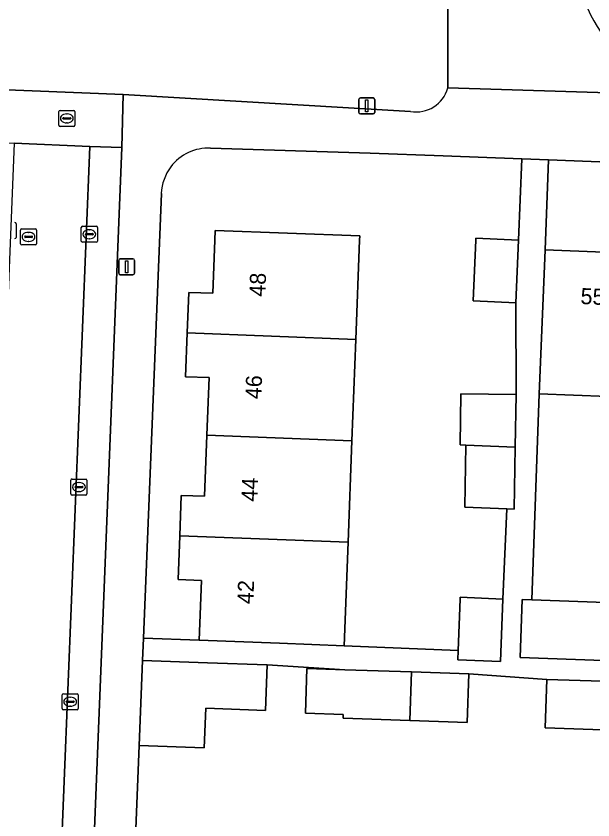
# Model space of a CAD drawing. Extents: x 160732 to 162107, y 387428 to 388479.
# Drawn here: x 161266.5 to 161302.4, y 387713.9 to 387764 of the extents above; entities that cross this region are included whole.
import ezdxf

# ---------------------------------------------------------------- set-up
doc = ezdxf.new("R2010")
doc.units = 0
for name, color, linetype in [('IMGEO_Erf', 7, 'Continuous'), ('IMGEO_Kolk', 7, 'Continuous'), ('IMGEO_Lichtmast', 7, 'Continuous'), ('IMGEO_Pand', 7, 'Continuous'), ('IMGEO_Pand_nummerreeks', 7, 'Continuous'), ('IMGEO_Parkeervlak_open', 7, 'Continuous'), ('IMGEO_Rijbaan_lokaal_gesloten', 7, 'Continuous'), ('IMGEO_Rijbaan_lokaal_open', 7, 'Continuous'), ('IMGEO_Rioolput', 7, 'Continuous'), ('IMGEO_Voetpad_open', 7, 'Continuous')]:
    doc.layers.add(name, color=color, linetype=linetype)

msp = doc.modelspace()

# ---------------------------------------------------------------- linework, layer by layer
at = {"layer": 'IMGEO_Erf'}
for points in [[(161293.367, 387759.476), (161293.305, 387802.486)], [(161170.782, 387763.221), (161261.267, 387759.549), (161273.154, 387759.067), (161291.049, 387758.02)], [(161297.977, 387755.057), (161293.09, 387755.247), (161288.543, 387755.424), (161278.594, 387755.733)], [(161275.527, 387752.907), (161274.418, 387725.228), (161277.881, 387725.089), (161278.023, 387728.809), (161276.57, 387728.864), (161276.674, 387731.584), (161276.77, 387734.111), (161278.219, 387734.055), (161278.364, 387737.848), (161278.501, 387741.439), (161277.034, 387741.495), (161277.138, 387744.222), (161277.234, 387746.747), (161278.728, 387746.69), (161278.855, 387750), (161278.878, 387750.606), (161287.89, 387750.262), (161287.88, 387750), (161287.638, 387743.824), (161287.403, 387737.505), (161287.162, 387731.186), (161286.916, 387724.745), (161294.01, 387724.449), (161294.144, 387727.655), (161294.149, 387727.774), (161296.807, 387727.655), (161297.054, 387733.272), (161294.434, 387733.372), (161294.498, 387737.235), (161294.139, 387737.249), (161294.192, 387740.439), (161297.632, 387740.382), (161297.618, 387746.105), (161294.96, 387746.215), (161295.118, 387750), (161295.123, 387750.119), (161297.781, 387750), (161297.977, 387755.057)], [(161362.938, 387752.535), (161299.645, 387754.992), (161299.428, 387749.397), (161303.095, 387749.244)], [(161303.332, 387740.259), (161299.054, 387740.438), (161298.611, 387727.602), (161304.918, 387727.384)], [(161303.582, 387719.489), (161299.444, 387719.628), (161299.545, 387722.651), (161294.679, 387722.994), (161294.577, 387719.971), (161290.996, 387720.091), (161286.85, 387720.231), (161286.858, 387720.461), (161284.506, 387720.54), (161284.599, 387723.333), (161286.951, 387723.254), (161282.126, 387723.549), (161282.025, 387720.719), (161278.291, 387720.853), (161278.203, 387718.392), (161274.15, 387718.538), (161273.401, 387699.85)]]:
    msp.add_lwpolyline(points, dxfattribs=at)
for centre, radius, start, end in [((161291.412, 387760.015), 2.028, 259.6818, 344.5863), ((161278.469, 387752.789), 2.946, 87.5703, 142.9389), ((161278.476, 387752.79), 2.952, 143.033, 177.7294)]:
    msp.add_arc(centre, radius, start, end, dxfattribs=at)
at = {"layer": 'IMGEO_Kolk'}
for p, q in [((161266.477, 387751.023), (161266.477, 387750.171)), ((161270.541, 387749.942), (161270.541, 387750.794)), ((161270.616, 387750.868), (161271.468, 387750.868)), ((161271.029, 387750.648), (161271.054, 387750.648)), ((161271.542, 387750.794), (161271.542, 387749.942)), ((161270.8, 387750.362), (161270.8, 387750.374)), ((161271.238, 387750.325), (161270.84, 387750.325)), ((161270.843, 387750.411), (161271.241, 387750.411)), ((161271.052, 387750.088), (161271.027, 387750.088)), ((161271.284, 387750.374), (161271.284, 387750.362)), ((161271.468, 387749.868), (161270.616, 387749.868)), ((161269.892, 387734.203), (161269.892, 387735.055)), ((161269.967, 387735.129), (161270.819, 387735.129)), ((161270.893, 387735.055), (161270.893, 387734.203)), ((161270.151, 387734.623), (161270.151, 387734.635)), ((161270.589, 387734.586), (161270.191, 387734.586)), ((161270.194, 387734.672), (161270.592, 387734.672)), ((161270.38, 387734.909), (161270.405, 387734.909)), ((161270.635, 387734.635), (161270.635, 387734.623)), ((161270.819, 387734.129), (161269.967, 387734.129)), ((161270.403, 387734.349), (161270.378, 387734.349)), ((161269.347, 387720.835), (161269.347, 387721.687)), ((161269.422, 387721.761), (161270.274, 387721.761)), ((161269.835, 387721.541), (161269.86, 387721.541)), ((161270.348, 387721.687), (161270.348, 387720.835)), ((161269.606, 387721.255), (161269.606, 387721.267)), ((161270.044, 387721.218), (161269.646, 387721.218)), ((161269.649, 387721.304), (161270.047, 387721.304)), ((161269.858, 387720.981), (161269.833, 387720.981)), ((161270.09, 387721.267), (161270.09, 387721.255)), ((161270.274, 387720.761), (161269.422, 387720.761))]:
    msp.add_line(p, q, dxfattribs=at)
for points in [[(161266.477, 387751.023), (161266.477, 387750.171)], [(161270.541, 387749.942), (161270.541, 387750.794)], [(161270.616, 387750.868), (161271.468, 387750.868)], [(161271.542, 387750.794), (161271.542, 387749.942)], [(161271.468, 387749.868), (161270.616, 387749.868)], [(161269.892, 387734.203), (161269.892, 387735.055)], [(161269.967, 387735.129), (161270.819, 387735.129)], [(161270.893, 387735.055), (161270.893, 387734.203)], [(161270.819, 387734.129), (161269.967, 387734.129)], [(161269.347, 387720.835), (161269.347, 387721.687)], [(161269.422, 387721.761), (161270.274, 387721.761)], [(161270.348, 387721.687), (161270.348, 387720.835)], [(161270.274, 387720.761), (161269.422, 387720.761)]]:
    msp.add_lwpolyline(points, dxfattribs=at)
for centre, radius, start, end in [((161266.401, 387751.021), 0.0765, 1.552, 88.448), ((161266.401, 387751.021), 0.0765, 1.552, 88.448), ((161270.618, 387750.792), 0.0765, 91.552, 178.448), ((161270.618, 387750.792), 0.0765, 91.552, 178.448), ((161271.466, 387750.792), 0.0765, 1.552, 88.448), ((161271.466, 387750.792), 0.0765, 1.552, 88.448), ((161266.401, 387750.173), 0.0765, 271.552, 358.448), ((161266.401, 387750.173), 0.0765, 271.552, 358.448), ((161270.84, 387750.371), 0.0403, 85.8775, 175.7526), ((161270.837, 387750.361), 0.0366, 178.938, 274.7102), ((161271.241, 387750.368), 0.043, 264.8664, 352.4533), ((161271.245, 387750.373), 0.0386, 1.7309, 96.639), ((161270.618, 387749.944), 0.0765, 181.552, 268.448), ((161270.618, 387749.944), 0.0765, 181.552, 268.448), ((161271.466, 387749.944), 0.0765, 271.552, 358.448), ((161271.466, 387749.944), 0.0765, 271.552, 358.448), ((161269.969, 387735.053), 0.0765, 91.552, 178.448), ((161269.969, 387735.053), 0.0765, 91.552, 178.448), ((161270.817, 387735.053), 0.0765, 1.552, 88.448), ((161270.817, 387735.053), 0.0765, 1.552, 88.448), ((161270.191, 387734.632), 0.0403, 85.8775, 175.7526), ((161270.188, 387734.622), 0.0366, 178.938, 274.7102), ((161270.592, 387734.629), 0.043, 264.8664, 352.4533), ((161270.596, 387734.634), 0.0386, 1.7309, 96.639), ((161269.969, 387734.205), 0.0765, 181.552, 268.448), ((161269.969, 387734.205), 0.0765, 181.552, 268.448), ((161270.817, 387734.205), 0.0765, 271.552, 358.448), ((161270.817, 387734.205), 0.0765, 271.552, 358.448), ((161269.424, 387721.685), 0.0765, 91.552, 178.448), ((161269.424, 387721.685), 0.0765, 91.552, 178.448), ((161270.272, 387721.685), 0.0765, 1.552, 88.448), ((161270.272, 387721.685), 0.0765, 1.552, 88.448), ((161269.646, 387721.264), 0.0403, 85.8775, 175.7526), ((161269.643, 387721.254), 0.0366, 178.938, 274.7102), ((161270.047, 387721.261), 0.043, 264.8664, 352.4533), ((161270.051, 387721.266), 0.0386, 1.7309, 96.639), ((161269.424, 387720.837), 0.0765, 181.552, 268.448), ((161269.424, 387720.837), 0.0765, 181.552, 268.448), ((161270.272, 387720.837), 0.0765, 271.552, 358.448), ((161270.272, 387720.837), 0.0765, 271.552, 358.448)]:
    msp.add_arc(centre, radius, start, end, dxfattribs=at)
for centre, major_axis, ratio, start_param, end_param in [((161271.028, 387750.368), (-0.387, 0.002), 0.722429, 4.712389, 7.853982), ((161271.053, 387750.368), (-0.39, 0.002), 0.717154, 1.570796, 4.712389), ((161270.379, 387734.629), (-0.387, 0.002), 0.722429, 4.712389, 7.853982), ((161270.404, 387734.629), (-0.39, 0.002), 0.717154, 1.570796, 4.712389), ((161269.834, 387721.261), (-0.387, 0.002), 0.722429, 4.712389, 7.853982), ((161269.859, 387721.261), (-0.39, 0.002), 0.717154, 1.570796, 4.712389)]:
    msp.add_ellipse(centre, major_axis=major_axis, ratio=ratio, start_param=start_param, end_param=end_param, dxfattribs=at)
at = {"layer": 'IMGEO_Lichtmast'}
for p, q in [((161287.829, 387757.956), (161287.829, 387758.756)), ((161287.829, 387758.756), (161287.829, 387757.956)), ((161287.929, 387758.856), (161288.719, 387758.856)), ((161288.719, 387758.856), (161287.929, 387758.856)), ((161288.819, 387758.756), (161288.819, 387757.956)), ((161288.819, 387757.956), (161288.819, 387758.756)), ((161288.719, 387757.856), (161287.929, 387757.856)), ((161287.929, 387757.856), (161288.719, 387757.856)), ((161272.869, 387747.943), (161272.869, 387748.743)), ((161272.869, 387748.743), (161272.869, 387747.943)), ((161272.969, 387748.843), (161273.759, 387748.843)), ((161273.759, 387748.843), (161272.969, 387748.843)), ((161273.859, 387748.743), (161273.859, 387747.943)), ((161273.859, 387747.943), (161273.859, 387748.743)), ((161273.759, 387747.843), (161272.969, 387747.843)), ((161272.969, 387747.843), (161273.759, 387747.843))]:
    msp.add_line(p, q, dxfattribs=at)
for points in [[(161288.249, 387758.731), (161288.399, 387758.731), (161288.399, 387757.981), (161288.249, 387757.981), (161288.249, 387758.731)], [(161273.289, 387748.718), (161273.439, 387748.718), (161273.439, 387747.968), (161273.289, 387747.968), (161273.289, 387748.718)]]:
    msp.add_lwpolyline(points, dxfattribs=at)
for centre, start, end in [((161287.929, 387758.756), 90, 180), ((161287.929, 387758.756), 90, 180), ((161288.719, 387758.756), 0, 90), ((161288.719, 387758.756), 360, 90), ((161287.929, 387757.956), 180, 270), ((161287.929, 387757.956), 180, 270), ((161288.719, 387757.956), 270, 0), ((161288.719, 387757.956), 270, 0), ((161272.969, 387748.743), 90, 180), ((161272.969, 387748.743), 90, 180), ((161273.759, 387748.743), 0, 90), ((161273.759, 387748.743), 360, 90), ((161272.969, 387747.943), 180, 270), ((161272.969, 387747.943), 180, 270), ((161273.759, 387747.943), 270, 0), ((161273.759, 387747.943), 270, 0)]:
    msp.add_arc(centre, 0.1, start, end, dxfattribs=at)
at = {"layer": 'IMGEO_Pand'}
for points in [[(161287.638, 387743.824), (161287.88, 387750), (161287.89, 387750.262), (161278.878, 387750.606), (161278.855, 387750), (161278.728, 387746.69), (161277.234, 387746.747), (161277.138, 387744.222)], [(161305.873, 387750), (161305.899, 387750.622), (161303.157, 387750.737), (161303.126, 387750), (161303.095, 387749.244), (161299.428, 387749.397), (161299.219, 387744.402), (161299.054, 387740.438), (161303.332, 387740.259), (161303.374, 387741.258), (161305.5, 387741.173)], [(161297.781, 387750), (161295.123, 387750.119), (161295.118, 387750), (161294.96, 387746.215), (161297.618, 387746.105)], [(161287.403, 387737.505), (161287.638, 387743.824), (161277.138, 387744.222), (161277.034, 387741.495), (161278.501, 387741.439), (161278.364, 387737.848)], [(161297.632, 387740.382), (161294.192, 387740.439), (161294.139, 387737.249), (161294.498, 387737.235), (161297.577, 387737.119)], [(161278.364, 387737.848), (161278.219, 387734.055), (161276.77, 387734.111), (161276.674, 387731.584), (161287.162, 387731.186), (161287.403, 387737.505)], [(161297.577, 387737.119), (161294.498, 387737.235), (161294.434, 387733.372), (161297.054, 387733.272), (161297.513, 387733.255)], [(161276.674, 387731.584), (161276.57, 387728.864), (161278.023, 387728.809), (161277.881, 387725.089), (161282.878, 387724.899), (161286.916, 387724.745), (161287.162, 387731.186)], [(161296.807, 387727.655), (161294.149, 387727.774), (161294.144, 387727.655), (161294.01, 387724.449), (161293.986, 387723.87), (161296.644, 387723.76)], [(161304.918, 387727.384), (161298.611, 387727.602), (161297.999, 387727.623), (161297.875, 387724.013), (161304.766, 387723.775)], [(161282.126, 387723.549), (161278.403, 387723.683), (161278.392, 387723.683), (161274.362, 387723.828), (161274.15, 387718.538), (161278.203, 387718.392), (161278.291, 387720.853), (161282.025, 387720.719)], [(161291.116, 387723.114), (161286.951, 387723.254), (161284.599, 387723.333), (161284.506, 387720.54), (161286.858, 387720.461), (161286.85, 387720.231), (161290.996, 387720.091)], [(161290.996, 387720.091), (161294.577, 387719.971), (161294.679, 387722.994), (161291.116, 387723.114)], [(161303.702, 387722.511), (161299.545, 387722.651), (161299.444, 387719.628), (161303.582, 387719.489)]]:
    msp.add_lwpolyline(points, close=True, dxfattribs=at)
at = {"layer": 'IMGEO_Parkeervlak_open'}
msp.add_lwpolyline([(161270.916, 387702.526), (161271.235, 387710.265), (161273.075, 387755.768), (161271.065, 387755.837), (161268.794, 387699.381)], dxfattribs=at)
at = {"layer": 'IMGEO_Rijbaan_lokaal_gesloten'}
msp.add_arc((161310.679, 387768.21), 9.396, 175.1143, 258.1471, dxfattribs=at)
at = {"layer": 'IMGEO_Rijbaan_lokaal_open'}
for points in [[(161271.065, 387755.837), (161266.349, 387756.032), (161264.992, 387722.272), (161264.897, 387719.726), (161264.893, 387719.616), (161264.888, 387719.507), (161264.221, 387703.574)], [(161264.196, 387702.972), (161264.025, 387699.309), (161268.792, 387699.134), (161268.794, 387699.381), (161271.065, 387755.837)]]:
    msp.add_lwpolyline(points, dxfattribs=at)
at = {"layer": 'IMGEO_Rioolput'}
for p, q in [((161269.141, 387757.156), (161269.141, 387758.008)), ((161269.216, 387758.082), (161270.068, 387758.082)), ((161270.142, 387758.008), (161270.142, 387757.156)), ((161269.4, 387757.576), (161269.4, 387757.588)), ((161269.838, 387757.539), (161269.44, 387757.539)), ((161269.443, 387757.625), (161269.841, 387757.625)), ((161269.629, 387757.862), (161269.654, 387757.862)), ((161269.884, 387757.588), (161269.884, 387757.576)), ((161270.068, 387757.082), (161269.216, 387757.082)), ((161269.652, 387757.302), (161269.627, 387757.302)), ((161266.754, 387749.779), (161266.754, 387750.631)), ((161266.829, 387750.705), (161267.681, 387750.705)), ((161267.242, 387750.485), (161267.267, 387750.485)), ((161267.755, 387750.631), (161267.755, 387749.779)), ((161267.013, 387750.199), (161267.013, 387750.211)), ((161267.451, 387750.162), (161267.053, 387750.162)), ((161267.056, 387750.248), (161267.454, 387750.248)), ((161267.497, 387750.211), (161267.497, 387750.199)), ((161267.681, 387749.705), (161266.829, 387749.705)), ((161267.265, 387749.925), (161267.24, 387749.925))]:
    msp.add_line(p, q, dxfattribs=at)
for points in [[(161269.141, 387757.156), (161269.141, 387758.008)], [(161269.216, 387758.082), (161270.068, 387758.082)], [(161270.142, 387758.008), (161270.142, 387757.156)], [(161270.068, 387757.082), (161269.216, 387757.082)], [(161266.754, 387749.779), (161266.754, 387750.631)], [(161266.829, 387750.705), (161267.681, 387750.705)], [(161267.755, 387750.631), (161267.755, 387749.779)], [(161267.681, 387749.705), (161266.829, 387749.705)]]:
    msp.add_lwpolyline(points, dxfattribs=at)
for centre, radius, start, end in [((161269.218, 387758.006), 0.0765, 91.552, 178.448), ((161269.218, 387758.006), 0.0765, 91.552, 178.448), ((161270.066, 387758.006), 0.0765, 1.552, 88.448), ((161270.066, 387758.006), 0.0765, 1.552, 88.448), ((161269.44, 387757.585), 0.0403, 85.8775, 175.7526), ((161269.437, 387757.575), 0.0366, 178.938, 274.7102), ((161269.841, 387757.582), 0.043, 264.8664, 352.4533), ((161269.845, 387757.587), 0.0386, 1.7309, 96.639), ((161269.218, 387757.158), 0.0765, 181.552, 268.448), ((161269.218, 387757.158), 0.0765, 181.552, 268.448), ((161270.066, 387757.158), 0.0765, 271.552, 358.448), ((161270.066, 387757.158), 0.0765, 271.552, 358.448), ((161266.831, 387750.629), 0.0765, 91.552, 178.448), ((161266.831, 387750.629), 0.0765, 91.552, 178.448), ((161267.679, 387750.629), 0.0765, 1.552, 88.448), ((161267.679, 387750.629), 0.0765, 1.552, 88.448), ((161267.053, 387750.208), 0.0403, 85.8775, 175.7526), ((161267.05, 387750.198), 0.0366, 178.938, 274.7102), ((161267.454, 387750.205), 0.043, 264.8664, 352.4533), ((161267.458, 387750.21), 0.0386, 1.7309, 96.639), ((161266.831, 387749.781), 0.0765, 181.552, 268.448), ((161266.831, 387749.781), 0.0765, 181.552, 268.448), ((161267.679, 387749.781), 0.0765, 271.552, 358.448), ((161267.679, 387749.781), 0.0765, 271.552, 358.448)]:
    msp.add_arc(centre, radius, start, end, dxfattribs=at)
for centre, major_axis, ratio, start_param, end_param in [((161269.628, 387757.582), (-0.387, 0.002), 0.722429, 4.712389, 7.853982), ((161269.653, 387757.582), (-0.39, 0.002), 0.717154, 1.570796, 4.712389), ((161267.241, 387750.205), (-0.387, 0.002), 0.722429, 4.712389, 7.853982), ((161267.266, 387750.205), (-0.39, 0.002), 0.717154, 1.570796, 4.712389)]:
    msp.add_ellipse(centre, major_axis=major_axis, ratio=ratio, start_param=start_param, end_param=end_param, dxfattribs=at)
at = {"layer": 'IMGEO_Voetpad_open'}
for points in [[(161293.564, 387807.793), (161293.305, 387802.486), (161293.367, 387759.476), (161308.749, 387759.014)], [(161170.695, 387760.141), (161193.746, 387759.211), (161195.272, 387759.149), (161232.72, 387757.637), (161234.166, 387757.579), (161256.169, 387756.691), (161259.515, 387756.527), (161259.656, 387756.534), (161264.34, 387756.081), (161266.349, 387756.032), (161271.065, 387755.837), (161273.075, 387755.768), (161273.154, 387759.067), (161261.267, 387759.549), (161170.782, 387763.221)], [(161291.049, 387758.02), (161273.154, 387759.067), (161273.075, 387755.768), (161271.235, 387710.265), (161270.916, 387702.526)], [(161308.749, 387759.014), (161293.367, 387759.476)], [(161278.594, 387755.733), (161288.543, 387755.424), (161293.09, 387755.247), (161297.977, 387755.057), (161299.645, 387754.992), (161362.938, 387752.535), (161365.476, 387752.411), (161391.456, 387751.23)], [(161304.766, 387723.775), (161297.875, 387724.013), (161297.999, 387727.623), (161298.611, 387727.602), (161299.054, 387740.438), (161299.219, 387744.402), (161299.428, 387749.397), (161299.645, 387754.992), (161297.977, 387755.057), (161297.781, 387750), (161297.618, 387746.105), (161297.632, 387740.382), (161297.577, 387737.119), (161297.513, 387733.255), (161297.054, 387733.272), (161296.807, 387727.655), (161296.644, 387723.76), (161293.986, 387723.87), (161294.01, 387724.449), (161286.916, 387724.745), (161282.878, 387724.899), (161277.881, 387725.089), (161274.418, 387725.228), (161274.362, 387723.828), (161278.392, 387723.683), (161278.403, 387723.683), (161282.126, 387723.549), (161286.951, 387723.254), (161291.116, 387723.114), (161294.679, 387722.994), (161299.545, 387722.651), (161303.702, 387722.511)], [(161274.362, 387723.828), (161274.418, 387725.228), (161275.527, 387752.907)], [(161273.401, 387699.85), (161274.15, 387718.538), (161274.362, 387723.828)]]:
    msp.add_lwpolyline(points, dxfattribs=at)
for centre, radius, start, end in [((161310.679, 387768.21), 9.396, 175.1143, 258.1471), ((161291.412, 387760.015), 2.028, 259.6818, 344.5863), ((161278.469, 387752.789), 2.946, 87.5703, 142.9389), ((161278.476, 387752.79), 2.952, 143.033, 177.7294)]:
    msp.add_arc(centre, radius, start, end, dxfattribs=at)

# ---------------------------------------------------------------- texts
at = {"layer": 'IMGEO_Pand_nummerreeks'}
for s, rotation, p in [('48', 87.7625, (161281.999, 387746.466)), ('55', 357.6795, (161301.624, 387746.024)), ('46', 87.7625, (161281.75, 387740.084)), ('44', 87.7625, (161281.501, 387733.705)), ('42', 87.7625, (161281.251, 387727.322))]:
    msp.add_text(s, height=1, rotation=rotation, dxfattribs=at).set_placement(p)

doc.saveas('drawing.dxf')
